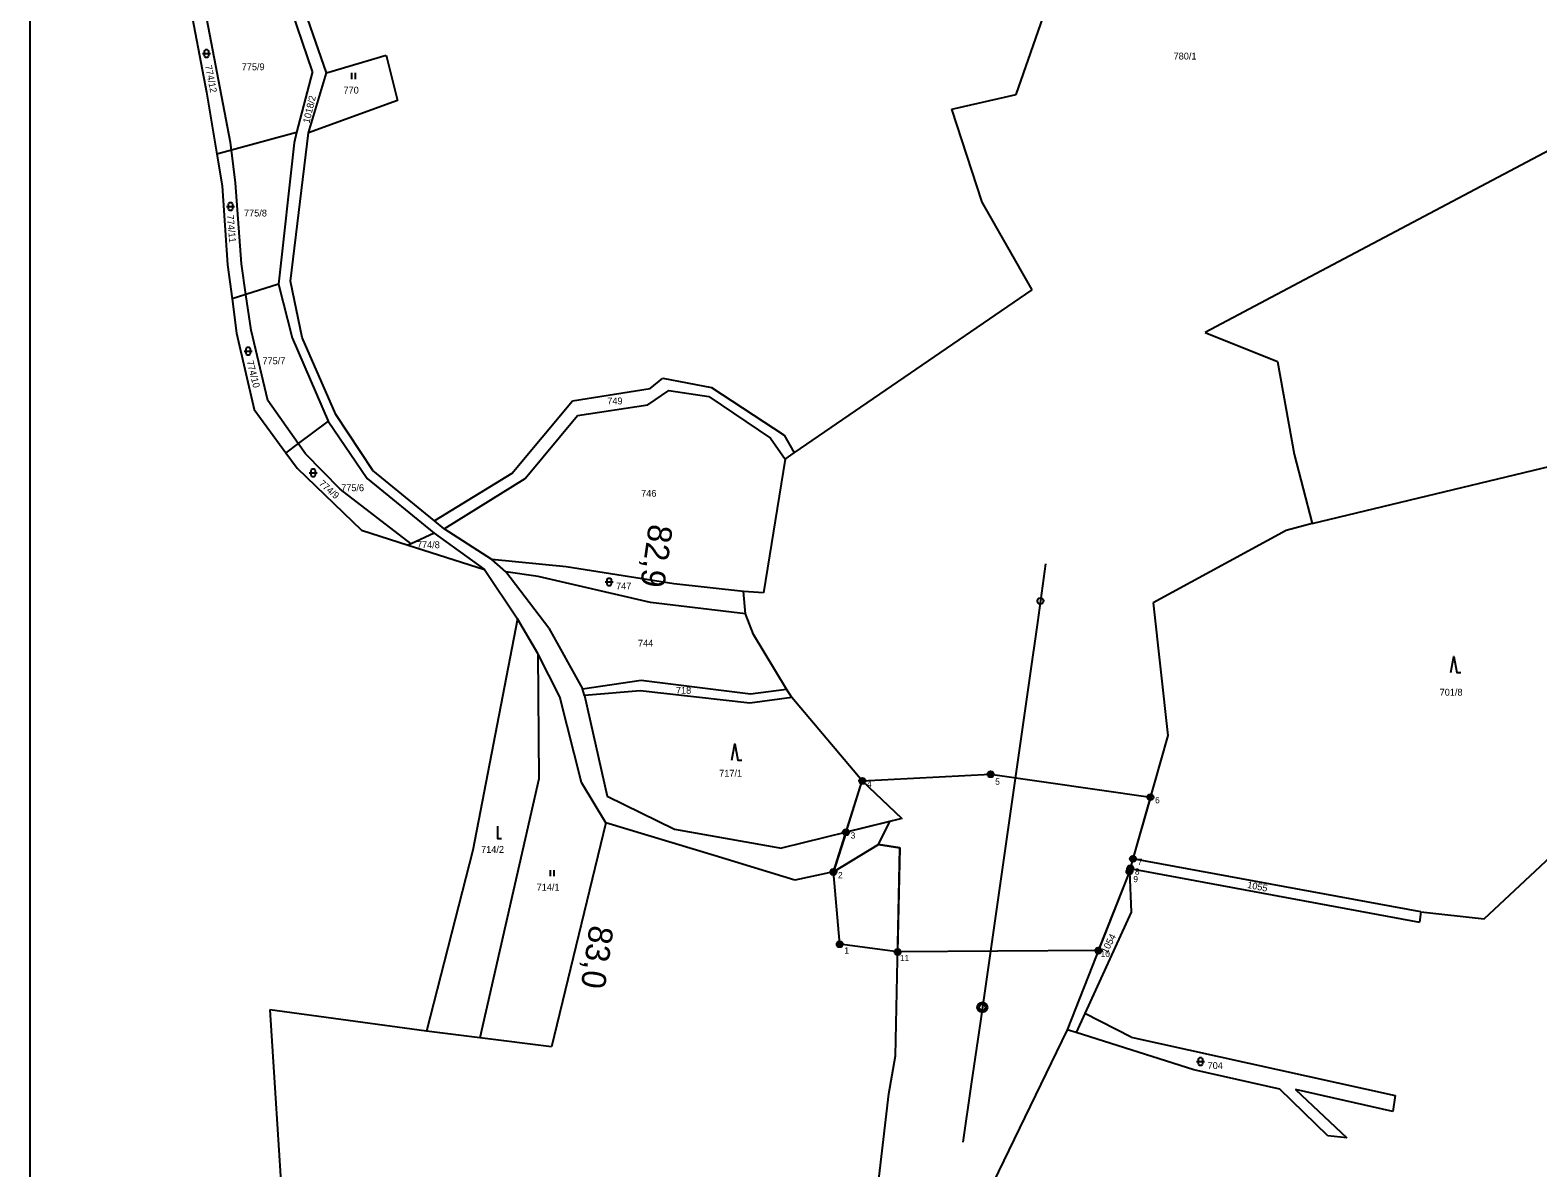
# Model space of a CAD drawing. Extents: x -801907 to -800293, y -1016964 to -1015684.
# Drawn here: x -801306.1 to -800931.6, y -1016616.9 to -1016334.3 of the extents above; entities that cross this region are included whole.
import ezdxf

# ---------------------------------------------------------------- set-up
doc = ezdxf.new("R2010")
doc.units = 0
for name, color, linetype in [('05a - kolej - svršek', 7, 'Continuous'), ('body', 7, 'Continuous'), ('cisla', 7, 'Continuous'), ('Default', 7, 'Continuous'), ('dočasné_zábory', 7, 'Continuous'), ('KN_HRANICE', 7, 'Continuous'), ('KN_KULTURY', 7, 'Continuous'), ('KN_PARCELY', 7, 'Continuous'), ('LEGENDA', 7, 'Continuous'), ('obvod_stavby', 7, 'Continuous'), ('Vrstva 7', 7, 'Continuous'), ('Železniční svršek', 7, 'Continuous')]:
    doc.layers.add(name, color=color, linetype=linetype)

# ---------------------------------------------------------------- blocks, each defined once
blk = doc.blocks.new('302')
at = {"layer": 'Default'}
blk.add_lwpolyline([(0, 3), (0, 0), (1, 0)], dxfattribs=at)
blk = doc.blocks.new('306')
at = {"layer": 'Default'}
for p, q in [((-0.5, 1.5), (-0.5, 0)), ((0.5, 0), (0.5, 1.5))]:
    blk.add_line(p, q, dxfattribs=at)
blk = doc.blocks.new('308')
at = {"layer": 'Default'}
blk.add_lwpolyline([(-0.75, 0), (0, 4), (0.75, 0), (1.75, 0)], dxfattribs=at)
blk = doc.blocks.new('316')
at = {"layer": 'Default'}
for points in [[(-1, 1), (0.27, 1), (1, 1)], [(-0.5, 1.5), (-0.4, 1.79), (-0.15, 1.97), (0.16, 1.97), (0.41, 1.79), (0.51, 1.5), (0.51, 0.5), (0.41, 0.21), (0.16, 0.03), (-0.15, 0.03), (-0.4, 0.21), (-0.5, 0.5), (-0.5, 1.5)]]:
    blk.add_lwpolyline(points, dxfattribs=at)
blk = doc.blocks.new('C512')
at = {"layer": 'Default'}
for radius in [1.25, 0.752]:
    blk.add_circle((0, 0), radius, dxfattribs=at)
blk = doc.blocks.new('C513_1')
at = {"layer": 'Default'}
blk.add_circle((0, 0), 0.75, dxfattribs=at)

msp = doc.modelspace()

# ---------------------------------------------------------------- linework, layer by layer
at = {"layer": 'body'}
for p, q in [((-801067.53, -1016519.1), (-801067.53, -1016519.1)), ((-801099.39, -1016520.76), (-801099.39, -1016520.76)), ((-801027.82, -1016524.78), (-801027.82, -1016524.78)), ((-801103.44, -1016533.5), (-801103.44, -1016533.5)), ((-801032.15, -1016540.1), (-801032.15, -1016540.1)), ((-801106.57, -1016543.36), (-801106.57, -1016543.36)), ((-801033.04, -1016543.25), (-801033.04, -1016543.25)), ((-801032.82, -1016542.48), (-801032.82, -1016542.48)), ((-801105.01, -1016561.32), (-801105.01, -1016561.32)), ((-801090.62, -1016563.22), (-801090.62, -1016563.22)), ((-801040.77, -1016562.91), (-801040.77, -1016562.91))]:
    msp.add_line(p, q, dxfattribs=at)
for centre, radius in [((-801067.53, -1016519.1), 0.75), ((-801067.53, -1016519.1), 0.35), ((-801099.39, -1016520.76), 0.75), ((-801099.39, -1016520.76), 0.35), ((-801027.82, -1016524.78), 0.75), ((-801027.82, -1016524.78), 0.35), ((-801103.44, -1016533.5), 0.75), ((-801103.44, -1016533.5), 0.35), ((-801032.82, -1016542.48), 0.75), ((-801032.15, -1016540.1), 0.75), ((-801032.15, -1016540.1), 0.35), ((-801106.57, -1016543.36), 0.75), ((-801106.57, -1016543.36), 0.35), ((-801033.04, -1016543.25), 0.75), ((-801033.04, -1016543.25), 0.35), ((-801032.82, -1016542.48), 0.35), ((-801105.01, -1016561.32), 0.75), ((-801105.01, -1016561.32), 0.35), ((-801090.62, -1016563.22), 0.75), ((-801090.62, -1016563.22), 0.35), ((-801040.77, -1016562.91), 0.75), ((-801040.77, -1016562.91), 0.35)]:
    msp.add_circle(centre, radius, dxfattribs=at)
at = {"layer": 'dočasné_zábory'}
for points in [[(-801103.44, -1016533.5), (-801099.39, -1016520.76), (-801089.6, -1016530.05), (-801103.44, -1016533.5)], [(-801103.44, -1016533.5), (-801106.57, -1016543.36), (-801095.34, -1016536.52), (-801092.56, -1016530.79), (-801103.44, -1016533.5), (-801106.57, -1016543.36)], [(-801106.57, -1016543.36), (-801095.34, -1016536.52), (-801090.08, -1016537.39), (-801090.62, -1016563.22), (-801105.01, -1016561.32), (-801106.57, -1016543.36)]]:
    msp.add_lwpolyline(points, dxfattribs=at)
at = {"layer": 'KN_HRANICE'}
for p, q in [((-801061.14, -1016350.27), (-801047.99, -1016312.24)), ((-801235.95, -1016344.57), (-801243.11, -1016323.66)), ((-801232.53, -1016344.87), (-801240.17, -1016322.77)), ((-801266.91, -1016325.63), (-801262.33, -1016349.67)), ((-801256.32, -1016362.14), (-801263.32, -1016325.64)), ((-801232.53, -1016344.87), (-801217.71, -1016340.48)), ((-801217.71, -1016340.48), (-801214.86, -1016351.72)), ((-800888.88, -1016342.96), (-800989.55, -1016396.29)), ((-801235.95, -1016344.57), (-801239.91, -1016359.71)), ((-801237.01, -1016359.78), (-801232.53, -1016344.87)), ((-801262.33, -1016349.67), (-801259.75, -1016365.1)), ((-801077.17, -1016353.9), (-801061.14, -1016350.27)), ((-801214.86, -1016351.72), (-801237.01, -1016359.78)), ((-801069.63, -1016376.99), (-801077.17, -1016353.9)), ((-801256.08, -1016364.1), (-801256.32, -1016362.14)), ((-801239.91, -1016359.71), (-801256.08, -1016364.1)), ((-801241.46, -1016396.62), (-801237.01, -1016359.78)), ((-801239.91, -1016359.71), (-801240.57, -1016362.23)), ((-801256.08, -1016364.1), (-801259.75, -1016365.1)), ((-801259.75, -1016365.1), (-801258.44, -1016372.97)), ((-801255.07, -1016372.22), (-801256.08, -1016364.1)), ((-801240.57, -1016362.23), (-801244.39, -1016397.38)), ((-801258.44, -1016372.97), (-801257.05, -1016392.52)), ((-801253.58, -1016392.3), (-801255.07, -1016372.22)), ((-801057.23, -1016398.8), (-801069.63, -1016376.99)), ((-801257.05, -1016392.52), (-801255.96, -1016400.96)), ((-801252.5, -1016399.89), (-801253.58, -1016392.3)), ((-801244.39, -1016397.38), (-801252.5, -1016399.89)), ((-801244.39, -1016397.38), (-801241.06, -1016410.72)), ((-801238.53, -1016410.63), (-801241.46, -1016396.62)), ((-801116.28, -1016439.27), (-801057.23, -1016398.8)), ((-800989.55, -1016396.29), (-801014.25, -1016409.38)), ((-801252.5, -1016399.89), (-801255.96, -1016400.96)), ((-801255.96, -1016400.96), (-801254.86, -1016409.5)), ((-801251.24, -1016408.75), (-801252.5, -1016399.89)), ((-801254.86, -1016409.5), (-801250.45, -1016428.49)), ((-801247.06, -1016426.26), (-801251.24, -1016408.75)), ((-801241.06, -1016410.72), (-801232.1, -1016431.41)), ((-801230.15, -1016429.74), (-801238.53, -1016410.63)), ((-801014.25, -1016409.38), (-800996.24, -1016416.56)), ((-800996.24, -1016416.56), (-800992.09, -1016439.62)), ((-801152.11, -1016423.31), (-801148.96, -1016420.73)), ((-801148.96, -1016420.73), (-801136.85, -1016423.02)), ((-801171.38, -1016426.36), (-801152.11, -1016423.31)), ((-801152.7, -1016427.3), (-801147.48, -1016423.8)), ((-801147.48, -1016423.8), (-801137.53, -1016425.26)), ((-801137.53, -1016425.26), (-801122.21, -1016435.63)), ((-801136.85, -1016423.02), (-801118.82, -1016434.86)), ((-801250.45, -1016428.49), (-801242.64, -1016439.22)), ((-801239.53, -1016436.92), (-801247.06, -1016426.26)), ((-801186.46, -1016444.4), (-801171.38, -1016426.36)), ((-801170.12, -1016429.97), (-801152.7, -1016427.3)), ((-801232.1, -1016431.41), (-801239.53, -1016436.92)), ((-801232.1, -1016431.41), (-801222.43, -1016445.62)), ((-801221.02, -1016443.67), (-801230.15, -1016429.74)), ((-801183.14, -1016445.59), (-801170.12, -1016429.97)), ((-801239.53, -1016436.92), (-801242.64, -1016439.22)), ((-801237.71, -1016439.5), (-801239.53, -1016436.92)), ((-801122.21, -1016435.63), (-801118.58, -1016440.85)), ((-801118.82, -1016434.86), (-801116.28, -1016439.27)), ((-801242.64, -1016439.22), (-801239.82, -1016443.1)), ((-801229.11, -1016448.31), (-801237.71, -1016439.5)), ((-801118.58, -1016440.85), (-801123.97, -1016474)), ((-801118.58, -1016440.85), (-801116.28, -1016439.27)), ((-800992.09, -1016439.62), (-800987.67, -1016456.78)), ((-801239.82, -1016443.1), (-801223.83, -1016458.49)), ((-801205.69, -1016456.16), (-801221.02, -1016443.67)), ((-801186.46, -1016444.4), (-801205.69, -1016456.16)), ((-800987.67, -1016456.78), (-800928.47, -1016442.57)), ((-801211.44, -1016461.84), (-801229.11, -1016448.31)), ((-801222.43, -1016445.62), (-801205.74, -1016459.23)), ((-801203.29, -1016458.12), (-801183.14, -1016445.59)), ((-801223.83, -1016458.49), (-801212.17, -1016462.19)), ((-801205.74, -1016459.23), (-801211.44, -1016461.84)), ((-801205.74, -1016459.23), (-801193.22, -1016468.21)), ((-801203.29, -1016458.12), (-801205.69, -1016456.16)), ((-801191.45, -1016465.73), (-801203.29, -1016458.12)), ((-800994.11, -1016458.53), (-801027.13, -1016476.53)), ((-800987.67, -1016456.78), (-800994.11, -1016458.53)), ((-801211.44, -1016461.84), (-801212.17, -1016462.19)), ((-801212.17, -1016462.19), (-801193.22, -1016468.21)), ((-801172.97, -1016467.58), (-801191.45, -1016465.73)), ((-801187.97, -1016468.83), (-801191.45, -1016465.73)), ((-801193.22, -1016468.21), (-801185.05, -1016480.49)), ((-801179.9, -1016469.93), (-801187.97, -1016468.83)), ((-801177.23, -1016482.84), (-801187.97, -1016468.83)), ((-801151.99, -1016476.42), (-801179.9, -1016469.93)), ((-801146.21, -1016471.77), (-801172.97, -1016467.58)), ((-801128.93, -1016473.72), (-801146.21, -1016471.77)), ((-801128.43, -1016479.26), (-801128.93, -1016473.72)), ((-801123.97, -1016474), (-801128.93, -1016473.72)), ((-801128.43, -1016479.26), (-801151.99, -1016476.42)), ((-801027.13, -1016476.53), (-801023.48, -1016509.45)), ((-801185.05, -1016480.49), (-801196.12, -1016537.94)), ((-801179.97, -1016489.06), (-801185.05, -1016480.49)), ((-801126.4, -1016484.41), (-801128.43, -1016479.26)), ((-801177.23, -1016482.84), (-801168.91, -1016497.9)), ((-801118.21, -1016497.93), (-801126.4, -1016484.41)), ((-801174.55, -1016499.85), (-801179.97, -1016489.06)), ((-801179.97, -1016489.06), (-801179.72, -1016520.25)), ((-801168.91, -1016497.9), (-801154.35, -1016495.73)), ((-801154.35, -1016495.73), (-801127.14, -1016499.11)), ((-801169.16, -1016521.13), (-801174.55, -1016499.85)), ((-801168.4, -1016499.55), (-801168.91, -1016497.9)), ((-801154.54, -1016498.41), (-801168.4, -1016499.55)), ((-801168.4, -1016499.55), (-801162.75, -1016524.53)), ((-801127.33, -1016501.46), (-801154.54, -1016498.41)), ((-801116.94, -1016500.02), (-801127.33, -1016501.46)), ((-801127.14, -1016499.11), (-801118.21, -1016497.93)), ((-801116.94, -1016500.02), (-801118.21, -1016497.93)), ((-801099.39, -1016520.76), (-801116.94, -1016500.02)), ((-801023.48, -1016509.45), (-801032.15, -1016540.1)), ((-801179.72, -1016520.25), (-801194.41, -1016584.56)), ((-801163.14, -1016531.12), (-801169.16, -1016521.13)), ((-801089.6, -1016530.05), (-801099.39, -1016520.76)), ((-801162.75, -1016524.53), (-801146.04, -1016532.72)), ((-801089.6, -1016530.05), (-801092.56, -1016530.79)), ((-801163.14, -1016531.12), (-801176.64, -1016586.76)), ((-801136.16, -1016539.31), (-801163.14, -1016531.12)), ((-801146.04, -1016532.72), (-801119.48, -1016537.49)), ((-801092.56, -1016530.79), (-801119.48, -1016537.49)), ((-801095.34, -1016536.52), (-801092.56, -1016530.79)), ((-801196.12, -1016537.94), (-801207.69, -1016582.91)), ((-801095.34, -1016536.52), (-801106.57, -1016543.36)), ((-801090.08, -1016537.39), (-801095.34, -1016536.52)), ((-801091.16, -1016589.05), (-801090.08, -1016537.39)), ((-801116.15, -1016545.38), (-801136.16, -1016539.31)), ((-801032.15, -1016540.1), (-801032.82, -1016542.48)), ((-800960.64, -1016553.29), (-801032.15, -1016540.1)), ((-800944.95, -1016554.98), (-800927.12, -1016538.33)), ((-801106.57, -1016543.36), (-801116.15, -1016545.38)), ((-801033.04, -1016543.25), (-801048.49, -1016582.57)), ((-801032.82, -1016542.48), (-801033.04, -1016543.25)), ((-801033.04, -1016543.25), (-801032.63, -1016553.37)), ((-801032.82, -1016542.48), (-800961, -1016555.83)), ((-801032.63, -1016553.37), (-801044.11, -1016578.55)), ((-800960.64, -1016553.29), (-800961, -1016555.83)), ((-800960.64, -1016553.29), (-800944.95, -1016554.98)), ((-801246.59, -1016577.62), (-801245.16, -1016599.53)), ((-801207.69, -1016582.91), (-801246.59, -1016577.62)), ((-801044.11, -1016578.55), (-801046.26, -1016583.28)), ((-801032.64, -1016584.41), (-801044.11, -1016578.55)), ((-801194.41, -1016584.56), (-801207.69, -1016582.91)), ((-801048.49, -1016582.57), (-801068.25, -1016623.2)), ((-801046.26, -1016583.28), (-801048.49, -1016582.57)), ((-801176.64, -1016586.76), (-801194.41, -1016584.56)), ((-801017.05, -1016592.55), (-801046.26, -1016583.28)), ((-801032.64, -1016584.41), (-800967.03, -1016598.88)), ((-801092.82, -1016598.49), (-801091.16, -1016589.05)), ((-800995.66, -1016597.3), (-801017.05, -1016592.55)), ((-800983.76, -1016608.9), (-800995.66, -1016597.3)), ((-800967.59, -1016602.85), (-800991.79, -1016597.39)), ((-800991.79, -1016597.39), (-800979, -1016609.4)), ((-801245.16, -1016599.53), (-801243.27, -1016628.57)), ((-801096.7, -1016632.06), (-801092.82, -1016598.49)), ((-800967.03, -1016598.88), (-800967.59, -1016602.85)), ((-800979, -1016609.4), (-800983.76, -1016608.9))]:
    msp.add_line(p, q, dxfattribs=at)
at = {"layer": 'LEGENDA'}
msp.add_lwpolyline([(-801306.12, -1016323.56), (-800712.12, -1016323.56), (-800712.12, -1016743.56), (-801306.12, -1016743.56)], close=True, dxfattribs=at)
at = {"layer": 'obvod_stavby'}
msp.add_lwpolyline([(-801099.39, -1016520.76), (-801067.53, -1016519.1), (-801027.82, -1016524.78), (-801032.15, -1016540.1), (-801032.82, -1016542.48), (-801033.04, -1016543.25), (-801040.77, -1016562.91), (-801090.62, -1016563.22), (-801105.01, -1016561.32), (-801106.57, -1016543.36), (-801099.39, -1016520.76)], dxfattribs=at)
at = {"layer": 'Železniční svršek'}
msp.add_lwpolyline([(-801053.85, -1016466.85), (-801055.91, -1016481.4), (-801057.88, -1016495.24), (-801059.95, -1016509.7), (-801062.03, -1016524.24), (-801064.02, -1016538.14), (-801066, -1016552.04), (-801068.07, -1016566.48), (-801070.07, -1016580.45), (-801072.31, -1016596.09), (-801074.39, -1016610.52)], dxfattribs=at)

# ---------------------------------------------------------------- block references
at = {"layer": '05a - kolej - svršek'}
for name, p, rotation in [('C513_1', (-801055.15, -1016476.05), -98.06617219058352), ('C512', (-801069.57, -1016576.99), -98.19442411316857)]:
    msp.add_blockref(name, p, dxfattribs=dict(at, rotation=rotation))
at = {"layer": 'KN_KULTURY'}
for name, p in [('316', (-801262.33, -1016341.07)), ('306', (-801225.78, -1016346.4)), ('316', (-801256.37, -1016379.06)), ('316', (-801251.96, -1016415)), ('316', (-801235.81, -1016445.22)), ('316', (-801162.28, -1016472.33)), ('308', (-800952.48, -1016493.82)), ('308', (-801131.06, -1016515.56)), ('302', (-801190.03, -1016535.01)), ('306', (-801176.4, -1016544.38)), ('316', (-801015.36, -1016591.46))]:
    msp.add_blockref(name, p, dxfattribs=at)

# ---------------------------------------------------------------- texts
at = {"layer": 'cisla'}
for s, p in [('  4', (-801099.39, -1016522.31)), ('  5', (-801067.53, -1016521.69)), ('  6', (-801027.82, -1016526.33)), ('  3', (-801103.44, -1016535.05)), ('  7', (-801032.15, -1016541.65)), ('  2', (-801106.57, -1016544.91)), ('  9', (-801033.21, -1016545.9)), ('  8', (-801032.82, -1016544.03)), ('  1', (-801105.01, -1016563.62)), (' 11', (-801090.62, -1016565.5)), (' 10', (-801040.77, -1016564.46))]:
    msp.add_text(s, height=1.552, dxfattribs=at).set_placement(p)
at = {"layer": 'KN_PARCELY'}
for s, rotation, p in [('774/12', 281.208, (-801262.69, -1016343.11)), ('1018/2', 76.604, (-801236.73, -1016357.51)), ('774/11', 275.421, (-801257.28, -1016380.18)), ('774/10', 284.187, (-801252.34, -1016416.53)), ('774/9', 318.565, (-801234.53, -1016447.1)), ('1055', 348.817, (-801003.87, -1016547.3)), ('1054', 62.624, (-801038.61, -1016563.8))]:
    msp.add_text(s, height=1.7, rotation=rotation, dxfattribs=at).set_placement(p)
for s, p in [('775/9', (-801253.56, -1016344.21)), ('780/1', (-801022.06, -1016341.55)), ('770', (-801228.28, -1016350.01)), ('775/8', (-801252.99, -1016380.54)), ('775/7', (-801248.41, -1016417.25)), ('749', (-801162.75, -1016427.21)), ('775/6', (-801228.86, -1016448.78)), ('746', (-801154.33, -1016450.16)), ('774/8', (-801210.04, -1016462.93)), ('747', (-801160.56, -1016473.18)), ('744', (-801155.13, -1016487.4)), ('718', (-801145.69, -1016499.1)), ('701/8', (-800955.97, -1016499.57)), ('717/1', (-801134.95, -1016519.69)), ('714/2', (-801194.09, -1016538.62)), ('714/1', (-801180.29, -1016547.99)), ('704', (-801013.62, -1016592.31))]:
    msp.add_text(s, height=1.7, dxfattribs=at).set_placement(p)
at = {"layer": 'Vrstva 7'}
for s, rotation, p in [('82,9', 261.9338, (-801152.38, -1016456.75)), ('83,0', 261.8056, (-801167.1, -1016556.4))]:
    msp.add_text(s, height=6, rotation=rotation, dxfattribs=at).set_placement(p)

doc.saveas('drawing.dxf')
